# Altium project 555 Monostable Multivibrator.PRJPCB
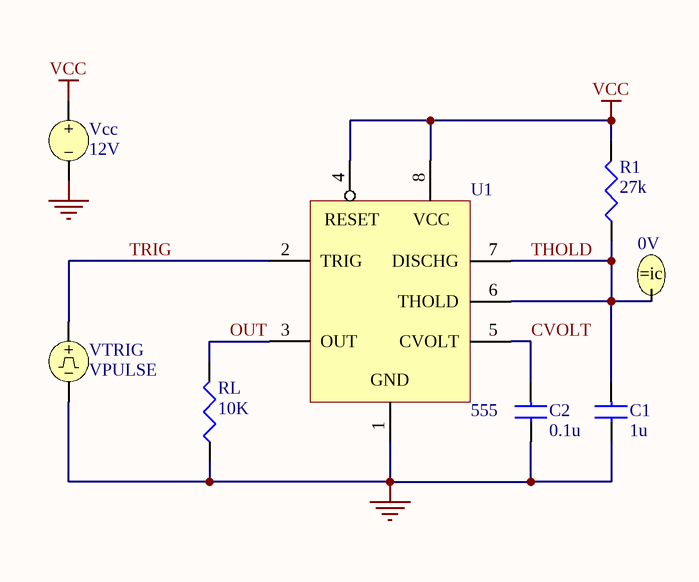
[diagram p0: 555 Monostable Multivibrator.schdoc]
1 sheet, 8 parts. Net scope: global (net labels, ports and power ports of the same name join across sheets).

## Sheet 555 Monostable Multivibrator.schdoc: 555 Monostable Multivibrator
size A4; Organization: Altium Limited; Address1: L3, 12a Rodborough Rd; Address2: Frenchs Forest; Address3: NSW; Address4: Australia 2086; DocumentNumber: 1; SheetNumber: 1; SheetTotal: 1

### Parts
C1  1u
C2  0.1u
IC1  0V
R1  27k
RL  10K
U1  555
Vcc  12V
VTRIG  VPULSE

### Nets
GND: C1.2 C2.2 RL.2(BOT) U1.1(GND) Vcc.2 VTRIG.2
VCC: R1.1(TOP) U1.4(RESET) U1.8(VCC) Vcc.1
CVOLT: C2.1 U1.5(CVOLT)
OUT: RL.1(TOP) U1.3(OUT)
THOLD: C1.1 IC1.1 R1.2(BOT) U1.6(THOLD) U1.7(DISCHG)
TRIG: U1.2(TRIG) VTRIG.1

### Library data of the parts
C1 C2 = CAP: Capacitor
IC1 = .IC: Initial Condition
R1 RL = RES: Resistor
U1 = 555: Timer
Vcc = VSRC: Voltage Source
VTRIG = VPULSE: Pulse Voltage Source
